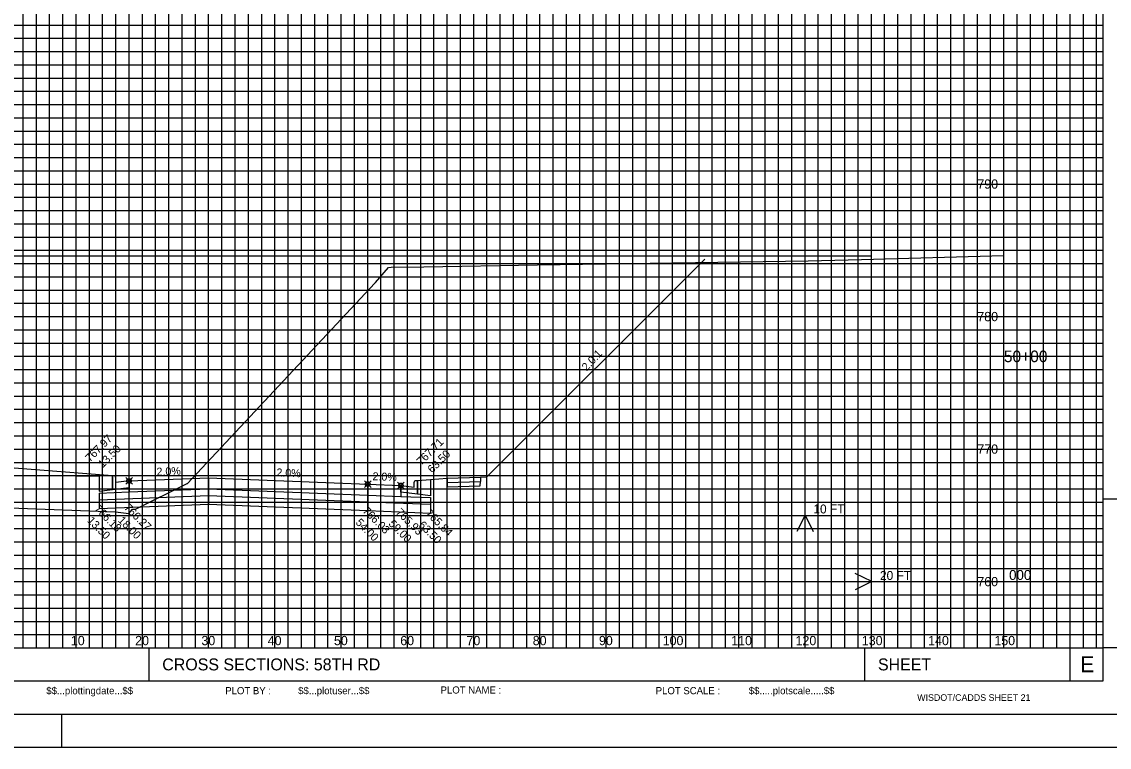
# Model space of a CAD drawing. Extents: x 578243 to 601557, y 174899 to 175559.
# Drawn here: x 600701.6 to 600865.7, y 174898.8 to 175008.3 of the extents above; entities that cross this region are included whole.
import ezdxf

# ---------------------------------------------------------------- set-up
doc = ezdxf.new("R2010")
doc.units = 0
for name, color, linetype in [('E_PROF_Grid', 7, 'Continuous'), ('E_PROF_GridMin', 7, 'Continuous'), ('P_CRDR_Label', 7, 'Continuous'), ('P_CRDR_Link', 7, 'Continuous'), ('P_E_XS_Ground', 7, 'Continuous'), ('P_RW_SlopeIntercepts', 7, 'Continuous'), ('P_XS_Text', 7, 'Continuous'), ('PLT_Sheet_Border', 7, 'Continuous'), ('PLT_Sheet_Info', 7, 'Continuous')]:
    doc.layers.add(name, color=color, linetype=linetype)

msp = doc.modelspace()

# ---------------------------------------------------------------- linework, layer by layer
at = {"layer": 'E_PROF_Grid'}
for p, q in [((600709.84, 174913.8), (600709.84, 175108.8)), ((600719.84, 174913.8), (600719.84, 175108.8)), ((600729.84, 174913.8), (600729.84, 175108.8)), ((600739.84, 174913.8), (600739.84, 175108.8)), ((600749.84, 174913.8), (600749.84, 175108.8)), ((600759.84, 174913.8), (600759.84, 175108.8)), ((600769.84, 174913.8), (600769.84, 175108.8)), ((600779.84, 174913.8), (600779.84, 175108.8)), ((600789.84, 174913.8), (600789.84, 175108.8)), ((600799.84, 174913.8), (600799.84, 175108.8)), ((600809.84, 174913.8), (600809.84, 175108.8)), ((600819.84, 174913.8), (600819.84, 175108.8)), ((600829.84, 174913.8), (600829.84, 175108.8)), ((600839.84, 174913.8), (600839.84, 175108.8)), ((600849.84, 174913.8), (600849.84, 175108.8)), ((600859.84, 174913.8), (600859.84, 175108.8)), ((600549.84, 175003.8), (600864.84, 175003.8)), ((600549.84, 174993.8), (600864.84, 174993.8)), ((600549.84, 174983.8), (600864.84, 174983.8)), ((600549.84, 174973.8), (600864.84, 174973.8)), ((600549.84, 174963.8), (600864.84, 174963.8)), ((600549.84, 174953.8), (600864.84, 174953.8)), ((600549.84, 174943.8), (600864.84, 174943.8)), ((600549.84, 174933.8), (600864.84, 174933.8)), ((600549.84, 174923.8), (600864.84, 174923.8))]:
    msp.add_line(p, q, dxfattribs=at)
at = {"layer": 'E_PROF_GridMin'}
for p, q in [((600701.84, 174913.8), (600701.84, 175108.8)), ((600703.84, 174913.8), (600703.84, 175108.8)), ((600705.84, 174913.8), (600705.84, 175108.8)), ((600707.84, 174913.8), (600707.84, 175108.8)), ((600711.84, 174913.8), (600711.84, 175108.8)), ((600713.84, 174913.8), (600713.84, 175108.8)), ((600715.84, 174913.8), (600715.84, 175108.8)), ((600717.84, 174913.8), (600717.84, 175108.8)), ((600721.84, 174913.8), (600721.84, 175108.8)), ((600723.84, 174913.8), (600723.84, 175108.8)), ((600725.84, 174913.8), (600725.84, 175108.8)), ((600727.84, 174913.8), (600727.84, 175108.8)), ((600731.84, 174913.8), (600731.84, 175108.8)), ((600733.84, 174913.8), (600733.84, 175108.8)), ((600735.84, 174913.8), (600735.84, 175108.8)), ((600737.84, 174913.8), (600737.84, 175108.8)), ((600741.84, 174913.8), (600741.84, 175108.8)), ((600743.84, 174913.8), (600743.84, 175108.8)), ((600745.84, 174913.8), (600745.84, 175108.8)), ((600747.84, 174913.8), (600747.84, 175108.8)), ((600751.84, 174913.8), (600751.84, 175108.8)), ((600753.84, 174913.8), (600753.84, 175108.8)), ((600755.84, 174913.8), (600755.84, 175108.8)), ((600757.84, 174913.8), (600757.84, 175108.8)), ((600761.84, 174913.8), (600761.84, 175108.8)), ((600763.84, 174913.8), (600763.84, 175108.8)), ((600765.84, 174913.8), (600765.84, 175108.8)), ((600767.84, 174913.8), (600767.84, 175108.8)), ((600771.84, 174913.8), (600771.84, 175108.8)), ((600773.84, 174913.8), (600773.84, 175108.8)), ((600775.84, 174913.8), (600775.84, 175108.8)), ((600777.84, 174913.8), (600777.84, 175108.8)), ((600781.84, 174913.8), (600781.84, 175108.8)), ((600783.84, 174913.8), (600783.84, 175108.8)), ((600785.84, 174913.8), (600785.84, 175108.8)), ((600787.84, 174913.8), (600787.84, 175108.8)), ((600791.84, 174913.8), (600791.84, 175108.8)), ((600793.84, 174913.8), (600793.84, 175108.8)), ((600795.84, 174913.8), (600795.84, 175108.8)), ((600797.84, 174913.8), (600797.84, 175108.8)), ((600801.84, 174913.8), (600801.84, 175108.8)), ((600803.84, 174913.8), (600803.84, 175108.8)), ((600805.84, 174913.8), (600805.84, 175108.8)), ((600807.84, 174913.8), (600807.84, 175108.8)), ((600811.84, 174913.8), (600811.84, 175108.8)), ((600813.84, 174913.8), (600813.84, 175108.8)), ((600815.84, 174913.8), (600815.84, 175108.8)), ((600817.84, 174913.8), (600817.84, 175108.8)), ((600821.84, 174913.8), (600821.84, 175108.8)), ((600823.84, 174913.8), (600823.84, 175108.8)), ((600825.84, 174913.8), (600825.84, 175108.8)), ((600827.84, 174913.8), (600827.84, 175108.8)), ((600831.84, 174913.8), (600831.84, 175108.8)), ((600833.84, 174913.8), (600833.84, 175108.8)), ((600835.84, 174913.8), (600835.84, 175108.8)), ((600837.84, 174913.8), (600837.84, 175108.8)), ((600841.84, 174913.8), (600841.84, 175108.8)), ((600843.84, 174913.8), (600843.84, 175108.8)), ((600845.84, 174913.8), (600845.84, 175108.8)), ((600847.84, 174913.8), (600847.84, 175108.8)), ((600851.84, 174913.8), (600851.84, 175108.8)), ((600853.84, 174913.8), (600853.84, 175108.8)), ((600855.84, 174913.8), (600855.84, 175108.8)), ((600857.84, 174913.8), (600857.84, 175108.8)), ((600861.84, 174913.8), (600861.84, 175108.8)), ((600863.84, 174913.8), (600863.84, 175108.8)), ((600549.84, 175007.8), (600864.84, 175007.8)), ((600549.84, 175005.8), (600864.84, 175005.8)), ((600549.84, 175001.8), (600864.84, 175001.8)), ((600549.84, 174999.8), (600864.84, 174999.8)), ((600549.84, 174997.8), (600864.84, 174997.8)), ((600549.84, 174995.8), (600864.84, 174995.8)), ((600549.84, 174991.8), (600864.84, 174991.8)), ((600549.84, 174989.8), (600864.84, 174989.8)), ((600549.84, 174987.8), (600864.84, 174987.8)), ((600549.84, 174985.8), (600864.84, 174985.8)), ((600549.84, 174981.8), (600864.84, 174981.8)), ((600549.84, 174979.8), (600864.84, 174979.8)), ((600549.84, 174977.8), (600864.84, 174977.8)), ((600549.84, 174975.8), (600864.84, 174975.8)), ((600549.84, 174971.8), (600864.84, 174971.8)), ((600549.84, 174969.8), (600864.84, 174969.8)), ((600549.84, 174967.8), (600864.84, 174967.8)), ((600549.84, 174965.8), (600864.84, 174965.8)), ((600549.84, 174961.8), (600864.84, 174961.8)), ((600549.84, 174959.8), (600864.84, 174959.8)), ((600549.84, 174957.8), (600864.84, 174957.8)), ((600549.84, 174955.8), (600864.84, 174955.8)), ((600549.84, 174951.8), (600864.84, 174951.8)), ((600549.84, 174949.8), (600864.84, 174949.8)), ((600549.84, 174947.8), (600864.84, 174947.8)), ((600549.84, 174945.8), (600864.84, 174945.8)), ((600549.84, 174941.8), (600864.84, 174941.8)), ((600549.84, 174939.8), (600864.84, 174939.8)), ((600549.84, 174937.8), (600864.84, 174937.8)), ((600549.84, 174935.8), (600864.84, 174935.8)), ((600549.84, 174931.8), (600864.84, 174931.8)), ((600549.84, 174929.8), (600864.84, 174929.8)), ((600549.84, 174927.8), (600864.84, 174927.8)), ((600549.84, 174925.8), (600864.84, 174925.8)), ((600549.84, 174921.8), (600864.84, 174921.8)), ((600549.84, 174919.8), (600864.84, 174919.8)), ((600549.84, 174917.8), (600864.84, 174917.8)), ((600549.84, 174915.8), (600864.84, 174915.8))]:
    msp.add_line(p, q, dxfattribs=at)
at = {"layer": 'P_CRDR_Label'}
for points in [[(600717.35, 174938.5), (600718.34, 174939.49)], [(600717.35, 174939.49), (600718.34, 174938.5)], [(600753.35, 174938.02), (600754.34, 174939.01)], [(600753.35, 174939.01), (600754.34, 174938.02)], [(600758.35, 174937.82), (600759.34, 174938.81)], [(600758.35, 174938.81), (600759.34, 174937.82)]]:
    msp.add_lwpolyline(points, dxfattribs=at)
for centre in [(600717.84, 174939), (600753.84, 174938.52), (600758.84, 174938.32)]:
    msp.add_circle(centre, 0.35, dxfattribs=at)
at = {"layer": 'P_CRDR_Link'}
msp.add_line((600804.69, 174972.46), (600771.84, 174939.61), dxfattribs=at)
for points in [[(600715.34, 174939.75), (600699.84, 174940.99)], [(600715.34, 174939.75), (600699.84, 174940.99)], [(600713.34, 174939.73), (600709.84, 174939.7)], [(600713.34, 174939.73), (600709.84, 174939.7)], [(600715.34, 174939.75), (600713.34, 174939.73)], [(600713.34, 174939.73), (600713.34, 174937.43)], [(600713.34, 174939.73), (600713.34, 174937.43)], [(600713.34, 174939.73), (600713.34, 174937.43)], [(600715.66, 174939.75), (600715.34, 174939.75)], [(600715.66, 174939.75), (600715.34, 174939.75)], [(600715.34, 174939.75), (600715.34, 174937.68)], [(600715.34, 174937.68), (600715.34, 174939.75)], [(600715.74, 174939.7), (600715.66, 174939.75)], [(600715.74, 174939.7), (600715.66, 174939.75)], [(600715.8, 174939.59), (600715.74, 174939.7)], [(600715.8, 174939.59), (600715.74, 174939.7)], [(600715.83, 174939.43), (600715.8, 174939.59)], [(600715.83, 174939.43), (600715.8, 174939.59)], [(600715.84, 174938.75), (600715.83, 174939.43)], [(600715.84, 174938.75), (600715.83, 174939.43)], [(600717.84, 174939), (600729.84, 174939.48)], [(600729.84, 174939.48), (600729.84, 174937.81)], [(600729.84, 174939.48), (600753.84, 174938.52)], [(600729.84, 174939.48), (600729.84, 174937.81)], [(600761.34, 174939.07), (600763.34, 174939.23)], [(600763.34, 174939.23), (600765.84, 174939.43)], [(600763.34, 174939.23), (600765.84, 174939.43)], [(600763.34, 174939.23), (600763.34, 174936.75)], [(600763.34, 174939.23), (600763.34, 174936.75)], [(600763.34, 174939.23), (600763.34, 174936.75)], [(600765.84, 174939.43), (600770.84, 174939.58)], [(600765.84, 174939.43), (600770.84, 174939.58)], [(600765.84, 174939.43), (600765.85, 174938.76)], [(600770.84, 174939.58), (600771.84, 174939.61)], [(600770.84, 174939.58), (600771.84, 174939.61)], [(600770.84, 174939.58), (600770.84, 174938.91)], [(600713.34, 174937.43), (600715.34, 174937.68)], [(600715.34, 174937.68), (600717.84, 174938)], [(600715.34, 174937.68), (600717.84, 174938)], [(600717.84, 174939), (600715.84, 174938.75)], [(600717.84, 174939), (600715.84, 174938.75)], [(600717.84, 174938), (600717.84, 174939)], [(600717.84, 174939), (600717.84, 174937.33)], [(600717.84, 174937.33), (600729.84, 174937.81)], [(600729.84, 174937.81), (600729.84, 174936.81)], [(600729.84, 174937.81), (600753.84, 174936.85)], [(600729.84, 174937.81), (600729.84, 174936.81)], [(600753.84, 174938.52), (600753.84, 174936.85)], [(600753.84, 174938.52), (600758.84, 174938.32)], [(600753.84, 174938.52), (600753.84, 174936.85)], [(600758.84, 174938.32), (600758.84, 174936.65)], [(600758.84, 174938.32), (600760.84, 174938.07)], [(600758.84, 174938.32), (600760.84, 174938.07)], [(600758.84, 174937.32), (600758.84, 174938.32)], [(600760.84, 174938.07), (600760.85, 174938.75)], [(600760.84, 174938.07), (600760.85, 174938.75)], [(600760.85, 174938.75), (600760.88, 174938.91)], [(600760.85, 174938.75), (600760.88, 174938.91)], [(600760.88, 174938.91), (600760.94, 174939.02)], [(600760.88, 174938.91), (600760.94, 174939.02)], [(600760.94, 174939.02), (600761.02, 174939.07)], [(600760.94, 174939.02), (600761.02, 174939.07)], [(600761.02, 174939.07), (600761.34, 174939.07)], [(600761.02, 174939.07), (600761.34, 174939.07)], [(600761.34, 174939.07), (600761.34, 174937)], [(600761.34, 174937), (600761.34, 174939.07)], [(600765.85, 174938.76), (600770.84, 174938.91)], [(600765.85, 174938.76), (600765.85, 174938.1)], [(600765.85, 174938.1), (600770.83, 174938.25)], [(600770.83, 174938.25), (600770.84, 174938.91)], [(600713.34, 174937.15), (600717.84, 174937.33)], [(600713.34, 174937.15), (600713.34, 174936.15)], [(600713.34, 174936.15), (600729.84, 174936.81)], [(600713.34, 174936.15), (600713.34, 174934.82)], [(600729.84, 174936.81), (600729.84, 174935.48)], [(600729.84, 174936.81), (600753.84, 174935.85)], [(600729.84, 174936.81), (600729.84, 174935.48)], [(600753.84, 174936.85), (600753.84, 174935.85)], [(600753.84, 174936.85), (600758.84, 174936.65)], [(600753.84, 174936.85), (600753.84, 174935.85)], [(600753.84, 174935.85), (600753.84, 174934.52)], [(600753.84, 174935.85), (600763.34, 174935.47)], [(600753.84, 174935.85), (600753.84, 174934.52)], [(600761.34, 174937), (600758.84, 174937.32)], [(600761.34, 174937), (600758.84, 174937.32)], [(600758.84, 174936.65), (600763.34, 174936.47)], [(600763.34, 174936.75), (600761.34, 174937)], [(600763.34, 174936.47), (600763.34, 174935.47)], [(600713.34, 174934.82), (600729.84, 174935.48)], [(600729.84, 174935.48), (600753.84, 174934.52)], [(600753.84, 174934.52), (600763.34, 174934.14)], [(600763.34, 174935.47), (600763.34, 174934.14)]]:
    msp.add_lwpolyline(points, dxfattribs=at)
at = {"layer": 'P_E_XS_Ground'}
msp.add_lwpolyline([(600699.84, 174934.95), (600711.84, 174934.47), (600715.78, 174934.31), (600717.78, 174934.06), (600718.36, 174934.73), (600718.78, 174934.73), (600718.78, 174934.73), (600726.62, 174938.59), (600726.63, 174938.59), (600726.65, 174938.6), (600726.66, 174938.6), (600754.94, 174968.85), (600755.03, 174968.94), (600756.99, 174971.23), (600756.99, 174971.23), (600757.38, 174971.24), (600762.33, 174971.32), (600779.47, 174971.61), (600820.3, 174972.22), (600828.36, 174972.41), (600849.84, 174973.02)], dxfattribs=at)
at = {"layer": 'P_RW_SlopeIntercepts'}
msp.add_line((600593.84, 174972.98), (600829.84, 174972.98), dxfattribs=at)
at = {"layer": 'PLT_Sheet_Border'}
for points in [[(600537.19, 174898.8), (600877.19, 174898.8), (600877.19, 175118.8), (600537.19, 175118.8)], [(600539.59, 174903.8), (600870.59, 174903.8), (600870.59, 175113.8), (600539.59, 175113.8)]]:
    msp.add_lwpolyline(points, close=True, dxfattribs=at)
at = {"layer": 'PLT_Sheet_Info'}
for p, q in [((600864.84, 174908.8), (600864.84, 175108.8)), ((600549.84, 174913.8), (600864.84, 174913.8)), ((600720.84, 174908.8), (600720.84, 174913.8)), ((600828.84, 174908.8), (600828.84, 174913.8)), ((600859.84, 174908.8), (600859.84, 174913.8)), ((600549.84, 174908.8), (600864.84, 174908.8)), ((600707.69, 174898.8), (600707.69, 174903.8)), ((600702.69, 174898.8), (600712.69, 174898.8))]:
    msp.add_line(p, q, dxfattribs=at)
msp.add_lwpolyline([(600864.84, 174936.3), (600870.34, 174936.3), (600870.34, 174913.8), (600864.84, 174913.8)], close=True, dxfattribs=at)
for points in [[(600819.84, 174933.84), (600818.6, 174931.36)], [(600819.84, 174923.8), (600819.84, 174933.84), (600821.08, 174931.36)], [(600829.89, 174923.8), (600827.4, 174925.04)], [(600819.84, 174923.8), (600829.89, 174923.8), (600827.4, 174922.55)]]:
    msp.add_lwpolyline(points, dxfattribs=at)

# ---------------------------------------------------------------- texts
at = {"layer": 'P_CRDR_Label'}
for s, rotation, p in [('2.0:1', 46.711, (600786.88, 174955.52)), ('767.97', 45, (600711.93, 174941.77)), ('13.50', 45, (600713.87, 174940.89)), ('767.71', 45, (600761.93, 174941.27)), ('63.50', 45, (600763.58, 174940.1)), ('2.0%', 2.2906, (600722, 174939.78)), ('2.0%', 357.7094, (600740.05, 174939.69)), ('2.0%', 357.7094, (600754.55, 174939.11)), ('766.18', 315, (600712.49, 174934.67)), ('766.27', 315, (600716.99, 174934.85)), ('766.03', 315, (600752.99, 174934.37)), ('765.93', 315, (600757.99, 174934.17)), ('765.84', 315, (600762.49, 174933.99)), ('13.50', 315, (600711.43, 174932.91)), ('18.00', 315, (600716.08, 174932.94)), ('54.00', 315, (600751.93, 174932.61)), ('59.00', 315, (600756.9, 174932.44)), ('63.50', 315, (600761.43, 174932.23))]:
    msp.add_text(s, height=1.2, rotation=rotation, dxfattribs=at).set_placement(p)
at = {"layer": 'P_XS_Text'}
for s, height, p in [('790', 1.4, (600845.84, 174983.1)), ('780', 1.4, (600845.84, 174963.1)), ('50+00', 1.75, (600849.84, 174956.92)), ('770', 1.4, (600845.84, 174943.1)), ('760', 1.4, (600845.84, 174923.1)), ('10', 1.4, (600709.05, 174914.2)), ('20', 1.4, (600718.75, 174914.2)), ('30', 1.4, (600728.75, 174914.2)), ('40', 1.4, (600738.75, 174914.2)), ('50', 1.4, (600748.75, 174914.2)), ('60', 1.4, (600758.75, 174914.2)), ('70', 1.4, (600768.75, 174914.2)), ('80', 1.4, (600778.75, 174914.2)), ('90', 1.4, (600788.74, 174914.2)), ('100', 1.4, (600798.36, 174914.2)), ('110', 1.4, (600808.7, 174914.2)), ('120', 1.4, (600818.41, 174914.2)), ('130', 1.4, (600828.41, 174914.2)), ('140', 1.4, (600838.41, 174914.2)), ('150', 1.4, (600848.41, 174914.2))]:
    msp.add_text(s, height=height, rotation=360, dxfattribs=at).set_placement(p)
at = {"layer": 'PLT_Sheet_Info'}
for s, height, p in [('  10 FT', 1.347, (600820.09, 174934.09)), ('  20 FT', 1.347, (600830.14, 174924.05)), ('     000', 1.5, (600847.84, 174924.05)), ('CROSS SECTIONS: 58TH RD                           ', 1.8, (600722.84, 174910.4)), ('SHEET ', 1.8, (600830.84, 174910.4)), ('E', 2.4, (600861.36, 174910.12)), ('PLOT NAME :                      ', 1.08, (600764.84, 174906.9)), ('$$.....plotscale.....$$', 1.08, (600811.34, 174906.8)), ('PLOT SCALE : ', 1.08, (600797.3, 174906.8)), ('WISDOT/CADDS SHEET 21', 1, (600836.76, 174905.8))]:
    msp.add_text(s, height=height, dxfattribs=at).set_placement(p)
for s, p in [('$$...plottingdate...$$', (600705.34, 174906.8)), ('$$...plotuser...$$', (600743.34, 174906.8)), ('PLOT BY :', (600732.34, 174906.8))]:
    msp.add_text(s, height=1.08, rotation=360, dxfattribs=at).set_placement(p)

doc.saveas('drawing.dxf')
